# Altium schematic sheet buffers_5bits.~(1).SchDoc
size A4
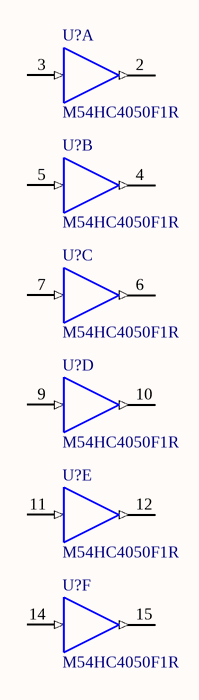
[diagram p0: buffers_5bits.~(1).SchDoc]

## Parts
(Parts that share a designator on the sheet are numbered #1, #2 ... from top to bottom, then left to right.)
U?#1  M54HC4050F1R  [DIP16]  (part A of 6)
U?#2  M54HC4050F1R  [DIP16]  (part B of 6)
U?#3  M54HC4050F1R  [DIP16]  (part C of 6)
U?#4  M54HC4050F1R  [DIP16]  (part D of 6)
U?#5  M54HC4050F1R  [DIP16]  (part E of 6)
U?#6  M54HC4050F1R  [DIP16]  (part F of 6)

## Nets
GND: U?#1.8(GND) U?#2.8(GND) U?#3.8(GND) U?#4.8(GND) U?#5.8(GND) U?#6.8(GND)
VCC: U?#1.1(VCC) U?#2.1(VCC) U?#3.1(VCC) U?#4.1(VCC) U?#5.1(VCC) U?#6.1(VCC)

Not connected (* = marked no-connect by the designer): U?#1 2(Y) 3(A); U?#2 4(Y) 5(A); U?#3 6(Y) 7(A); U?#4 9(A) 10(Y); U?#5 11(A) 12(Y); U?#6 14(A) 15(Y)

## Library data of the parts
U?#1-U?#6 = M54HC4050F1R: Hex Buffer/Converter Non-Inverting; Note: Pins 13 and 16 are not connected and not drawn.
